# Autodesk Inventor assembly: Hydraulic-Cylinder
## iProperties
Company: Autodesk, Inc.
Created: 2004-06
Part Number: Hydraulic-Cylinder
Document SubType Name: Assembly
Designer: Autodesk
Manufacturer: Standard
Standards Organization: Custom
Author: Autodesk Inc.
Subject: Autodesk Inventor
